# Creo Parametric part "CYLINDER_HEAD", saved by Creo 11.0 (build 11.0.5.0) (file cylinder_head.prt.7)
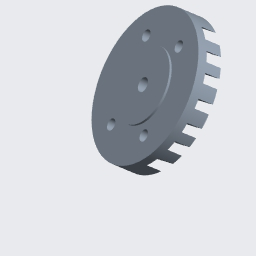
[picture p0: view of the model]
Materials in the file: 10038_S235JR

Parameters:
  MATERIAL = "10038_S235JR"
  PTC_MATERIAL_NAME = "10038_S235JR"
  PTC_MASTER_MATERIAL = "10038_S235JR"
  SELECT_EN_NAME = "S235JR"
  SELECT_DIN_NAME = "RSt37-2"
  SELECT_MATERIAL_NUMBER = "1.0038"
  SELECT_ASTM_NAME = "A 283 M Grade 2"
  MATERIAL_GROUP = "ME_ST_Baustahl"
  STANDARD_EN_DELIVERYSPEC = "DIN EN 10025-2"
  STANDARD_DIN_DELIVERYSPEC = "DIN EN 10025-2"

Other parameters: GEWICHT

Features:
  1. datum plane "RIGHT"
  2. datum plane "TOP"
  3. datum plane "FRONT"
  4. coordinate system
  5. datum axis
  6. datum axis
  7. datum axis
  8. revolve "Revolve 1"
  9. pattern "Pattern 1"
  10. extruded cut "Extrude 1"
  11. extruded cut "Extrude 1 [2]"
  12. extruded cut "Extrude 1 [3]"
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
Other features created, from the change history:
  mirror "Mirror 1"
  pattern "Pattern 1 (2)"
  extruded cut "Extrude 1 (2) [1]"
  extruded cut "Extrude 1 (2) [2]"
  extruded cut "Extrude 1 (2) [3]"
  mirror "Mirror 2"
  pattern "Pattern 1 (3)"
  extruded cut "Extrude 1 (3) [1]"
  extruded cut "Extrude 1 (3) [2]"
  extruded cut "Extrude 1 (3) [3]"
  mirror "Mirror 3"
  pattern "Pattern 1 (4)"
  extruded cut "Extrude 1 (4) [1]"
  extruded cut "Extrude 1 (4) [2]"
  extruded cut "Extrude 1 (4) [3]"
  extruded cut "Extrude 2"
  extruded cut "Extrude 3"
  mirror "Mirror 4"
  extruded cut "Extrude 3 (2)"
  mirror "Mirror 5"
  extruded cut "Extrude 3 (3)"
  mirror "Mirror 6"
  extruded cut "Extrude 3 (4)"
  extruded cut "Extrude 4"
  extruded cut "Extrude 5"
  mirror "Mirror 7"
  extruded cut "Extrude 5 (2)"
  mirror "Mirror 8"
  extruded cut "Extrude 5 (3)"
  mirror "Mirror 9"
  extruded cut "Extrude 5 (4)"
  extruded cut "Extrude 1 [4]" (2 times)
  extruded cut "Extrude 1 (2) [4]"
  extruded cut "Extrude 1 (3) [4]"
  extruded cut "Extrude 1 (4) [4]"
  extruded cut "Extrude 9"
  extruded cut "Extrude 6 [4]"
  extruded cut "Extrude 7 [4]"
  extruded cut "Extrude 8 [4]"
  datum plane "DTM1"
  extrusion "Extrude 9"
  mirror "Mirror 10"
  extruded cut "Extrude 9 (2)"
  extrusion "Extrude 10"
  hole "Hole 1"

Other named items: A_Y, A_X, A_Z, CS0

Layers: BEZUGSACHSEN, BEZUGSEBENEN, BOHRUNGEN

Surfaces: 30 plane, 13 cylinder, 2 cone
